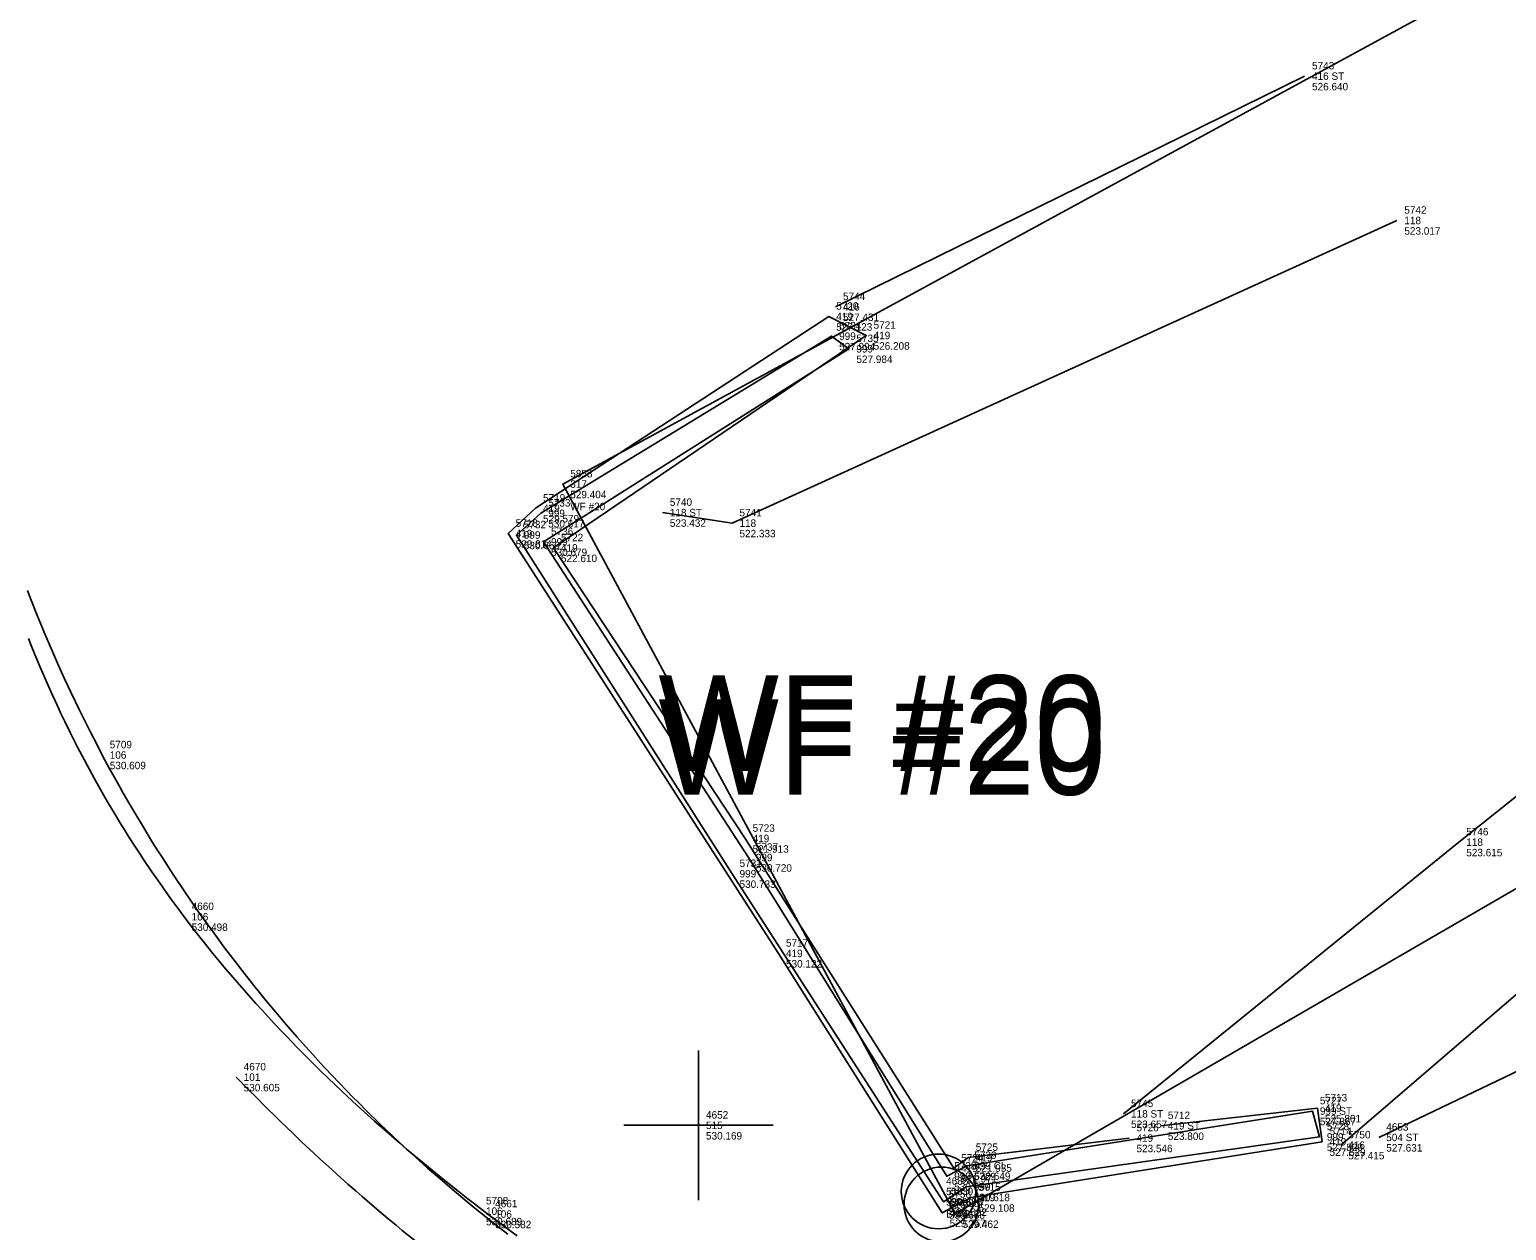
# Model space of a CAD drawing. Extents: x 5447 to 709667, y 4528 to 375505.
# Drawn here: x 705428.87 to 705478.33, y 375271.74 to 375311.93 of the extents above; entities that cross this region are included whole.
import ezdxf

# ---------------------------------------------------------------- set-up
doc = ezdxf.new("R2010")
doc.units = 0
for name, color, linetype in [('SV_BKLN_BKLN', 7, 'Continuous'), ('SV_CTRL_BM', 7, 'Continuous'), ('SV_DRAN_END_WALL', 7, 'Continuous'), ('SV_DRAN_RIPRAP', 7, 'Continuous'), ('SV_GDRL_GR', 7, 'Continuous'), ('SV_NODES_ACTIVE_POINT', 7, 'Continuous'), ('SV_NODES_DESCRIPTION', 7, 'Continuous'), ('SV_NODES_ELEVATION', 7, 'Continuous'), ('SV_NODES_PT_NUMBER', 7, 'Continuous'), ('SV_ROAD_BITRD', 7, 'Continuous'), ('SV_SURF_SPOT', 7, 'Continuous'), ('SV_SURVEY_NOTES', 7, 'Continuous'), ('SV_TREE_TREELN', 7, 'Continuous'), ('SV_WATR_INWETF', 7, 'Continuous'), ('SV_WATR_STREAM', 7, 'Continuous')]:
    doc.layers.add(name, color=color, linetype=linetype)

msp = doc.modelspace()

# ---------------------------------------------------------------- linework, layer by layer
at = {"layer": 'SV_BKLN_BKLN'}
msp.add_lwpolyline([(705471.836, 375275.737), (705472.07, 375274.872), (705460.245, 375273.195), (705459.478, 375272.702), (705452.401, 375283.681), (705445.176, 375295.017), (705445.995, 375295.744), (705455.735, 375301.673), (705456.314, 375301.249), (705446.088, 375294.787), (705452.947, 375284.223), (705459.591, 375273.555), (705460.263, 375273.908), (705471.836, 375275.737)], dxfattribs=at)
at = {"layer": 'SV_CTRL_BM'}
for p, q in [((705459.318, 375273.045), (705459.318, 375273.045)), ((705459.41, 375272.611), (705459.41, 375272.611))]:
    msp.add_line(p, q, dxfattribs=at)
for centre in [(705459.318, 375273.045), (705459.41, 375272.611)]:
    msp.add_circle(centre, 1.25, dxfattribs=at)
at = {"layer": 'SV_DRAN_END_WALL'}
msp.add_lwpolyline([(705466.744, 375275.244), (705472.005, 375275.833), (705472.16, 375274.71), (705460.403, 375272.842), (705459.437, 375272.33), (705453.955, 375281.014), (705444.904, 375295.066), (705445.82, 375295.911), (705455.638, 375302.332), (705456.889, 375301.695), (705446.42, 375294.585), (705452.839, 375284.859), (705459.823, 375273.82), (705460.311, 375274.178), (705465.695, 375274.834)], dxfattribs=at)
at = {"layer": 'SV_DRAN_RIPRAP'}
for points in [[(705471.573, 375310.375), (705455.866, 375302.655)], [(705489.353, 375288.542), (705480.464, 375281.19), (705472.788, 375274.596)]]:
    msp.add_lwpolyline(points, dxfattribs=at)
at = {"layer": 'SV_GDRL_GR'}
for points in [[(705444.893, 375271.617), (705444.498, 375271.922), (705444.302, 375272.076), (705444.041, 375272.283), (705443.911, 375272.388), (705443.531, 375272.697), (705443.028, 375273.117), (705442.779, 375273.329), (705442.532, 375273.543), (705442.203, 375273.83), (705442.04, 375273.975), (705441.555, 375274.414), (705441.235, 375274.71), (705440.812, 375275.11), (705440.602, 375275.311), (705440.134, 375275.77), (705439.929, 375275.975), (705439.656, 375276.251), (705439.52, 375276.39), (705439.217, 375276.705), (705439.017, 375276.916), (705438.752, 375277.199), (705438.62, 375277.341), (705438.358, 375277.628), (705438.012, 375278.013), (705437.841, 375278.207), (705437.459, 375278.647), (705437.175, 375278.98), (705436.802, 375279.427), (705436.618, 375279.653), (705436.343, 375279.993), (705435.982, 375280.451), (705435.803, 375280.681), (705435.406, 375281.204), (705435.21, 375281.467), (705434.952, 375281.82), (705434.823, 375281.998), (705434.569, 375282.354), (705434.236, 375282.833), (705434.071, 375283.075), (705433.705, 375283.621), (705433.525, 375283.896), (705433.287, 375284.264), (705433.17, 375284.449), (705432.995, 375284.728), (705432.765, 375285.101), (705432.651, 375285.289), (705432.397, 375285.713), (705432.231, 375285.997), (705432.012, 375286.378), (705431.903, 375286.569), (705431.663, 375287.001), (705431.544, 375287.217), (705431.387, 375287.508), (705431.31, 375287.653), (705431.133, 375287.989), (705430.901, 375288.439), (705430.787, 375288.665), (705430.534, 375289.175), (705430.41, 375289.431), (705430.247, 375289.774), (705430.167, 375289.946), (705430.047, 375290.205), (705429.89, 375290.551), (705429.812, 375290.724), (705429.64, 375291.116), (705429.527, 375291.377), (705429.379, 375291.727), (705429.306, 375291.902), (705429.145, 375292.298), (705428.909, 375292.894), (705428.807, 375293.16)], [(705428.833, 375291.553), (705428.925, 375291.324), (705429.049, 375291.018), (705429.112, 375290.866), (705429.225, 375290.597), (705429.38, 375290.239), (705429.458, 375290.061), (705429.637, 375289.661), (705429.728, 375289.463), (705429.851, 375289.199), (705429.914, 375289.067), (705430.056, 375288.771), (705430.248, 375288.38), (705430.346, 375288.185), (705430.495, 375287.893), (705430.698, 375287.507), (705430.8, 375287.314), (705431.035, 375286.884), (705431.195, 375286.598), (705431.411, 375286.219), (705431.521, 375286.031), (705431.772, 375285.609), (705431.9, 375285.399), (705432.072, 375285.121), (705432.159, 375284.982), (705432.335, 375284.705), (705432.573, 375284.338), (705432.694, 375284.155), (705432.97, 375283.747), (705433.11, 375283.543), (705433.298, 375283.273), (705433.393, 375283.139), (705433.61, 375282.838), (705433.903, 375282.438), (705434.052, 375282.24), (705434.366, 375281.828), (705434.579, 375281.556), (705434.723, 375281.375), (705435.013, 375281.015), (705435.233, 375280.747), (705435.382, 375280.569), (705435.681, 375280.215), (705435.833, 375280.038), (705436.139, 375279.688), (705436.45, 375279.34), (705436.659, 375279.11), (705437.082, 375278.653), (705437.323, 375278.397), (705437.485, 375278.228), (705437.812, 375277.891), (705437.976, 375277.724), (705438.308, 375277.391), (705438.644, 375277.061), (705438.869, 375276.843), (705439.325, 375276.409), (705439.497, 375276.248), (705439.844, 375275.927), (705440.194, 375275.609), (705440.429, 375275.398), (705440.902, 375274.981), (705441.261, 375274.671), (705441.502, 375274.466), (705441.986, 375274.059), (705442.23, 375273.858), (705442.721, 375273.458), (705443.216, 375273.064), (705443.549, 375272.804), (705443.771, 375272.632), (705444.218, 375272.29), (705444.876, 375271.799), (705445.208, 375271.556)]]:
    msp.add_lwpolyline(points, dxfattribs=at)
at = {"layer": 'SV_NODES_ACTIVE_POINT'}
for p, q in [((705471.573, 375310.375), (705471.573, 375310.375)), ((705474.664, 375305.545), (705474.664, 375305.545)), ((705455.866, 375302.655), (705455.866, 375302.655)), ((705455.638, 375302.332), (705455.638, 375302.332)), ((705455.735, 375301.673), (705455.735, 375301.673)), ((705456.889, 375301.695), (705456.889, 375301.695)), ((705456.314, 375301.249), (705456.314, 375301.249)), ((705446.731, 375296.722), (705446.731, 375296.722)), ((705445.82, 375295.911), (705445.82, 375295.911)), ((705445.995, 375295.744), (705445.995, 375295.744)), ((705450.066, 375295.767), (705450.066, 375295.767)), ((705444.904, 375295.066), (705444.904, 375295.066)), ((705445.176, 375295.017), (705445.176, 375295.017)), ((705452.398, 375295.415), (705452.398, 375295.415)), ((705446.088, 375294.787), (705446.088, 375294.787)), ((705446.42, 375294.585), (705446.42, 375294.585)), ((705431.31, 375287.653), (705431.31, 375287.653)), ((705452.839, 375284.859), (705452.839, 375284.859)), ((705476.737, 375284.738), (705476.737, 375284.738)), ((705452.947, 375284.223), (705452.947, 375284.223)), ((705452.401, 375283.681), (705452.401, 375283.681)), ((705434.052, 375282.24), (705434.052, 375282.24)), ((705453.955, 375281.014), (705453.955, 375281.014)), ((705435.795, 375276.871), (705435.795, 375276.871)), ((705465.513, 375275.644), (705465.513, 375275.644)), ((705471.836, 375275.737), (705471.836, 375275.737)), ((705472.005, 375275.833), (705472.005, 375275.833)), ((705466.744, 375275.244), (705466.744, 375275.244)), ((705465.695, 375274.834), (705465.695, 375274.834)), ((705472.07, 375274.872), (705472.07, 375274.872)), ((705472.16, 375274.71), (705472.16, 375274.71)), ((705474.058, 375274.855), (705474.058, 375274.855)), ((705460.311, 375274.178), (705460.311, 375274.178)), ((705472.788, 375274.596), (705472.788, 375274.596)), ((705459.823, 375273.82), (705459.823, 375273.82)), ((705460.263, 375273.908), (705460.263, 375273.908)), ((705459.591, 375273.555), (705459.591, 375273.555)), ((705460.245, 375273.195), (705460.245, 375273.195)), ((705459.478, 375272.702), (705459.478, 375272.702)), ((705460.403, 375272.842), (705460.403, 375272.842)), ((705443.911, 375272.388), (705443.911, 375272.388)), ((705444.218, 375272.29), (705444.218, 375272.29)), ((705459.437, 375272.33), (705459.437, 375272.33)), ((705459.867, 375272.301), (705459.867, 375272.301))]:
    msp.add_line(p, q, dxfattribs=at)
at = {"layer": 'SV_ROAD_BITRD'}
msp.add_lwpolyline([(705441.774, 375271.401), (705441.356, 375271.742), (705441.147, 375271.914), (705440.87, 375272.144), (705440.732, 375272.26), (705440.423, 375272.522), (705440.012, 375272.875), (705439.808, 375273.053), (705439.536, 375273.292), (705439.176, 375273.613), (705438.996, 375273.775), (705438.594, 375274.141), (705438.394, 375274.326), (705438.128, 375274.574), (705437.995, 375274.699), (705437.698, 375274.981), (705437.303, 375275.361), (705437.107, 375275.552), (705436.813, 375275.841), (705436.424, 375276.23), (705436.23, 375276.426), (705435.795, 375276.871)], dxfattribs=at)
at = {"layer": 'SV_SURF_SPOT'}
for p, q in [((705451.277, 375272.758), (705451.277, 375277.76)), ((705448.776, 375275.259), (705453.778, 375275.259)), ((705451.277, 375275.259), (705451.277, 375275.259))]:
    msp.add_line(p, q, dxfattribs=at)
at = {"layer": 'SV_TREE_TREELN'}
msp.add_lwpolyline([(705474.058, 375274.855), (705495.162, 375284.95), (705524.723, 375284.239), (705558.01, 375282.679), (705583.345, 375279.879), (705602.913, 375276.221)], dxfattribs=at)
at = {"layer": 'SV_WATR_INWETF'}
msp.add_lwpolyline([(705578.39, 375331.311), (705524.349, 375309.659), (705459.867, 375272.301), (705446.731, 375296.722), (705543.238, 375349.235), (705597.77, 375381.862)], dxfattribs=at)
at = {"layer": 'SV_WATR_STREAM'}
for points in [[(705450.066, 375295.767), (705452.398, 375295.415), (705474.664, 375305.545)], [(705465.513, 375275.644), (705476.737, 375284.738), (705486.336, 375292.375)]]:
    msp.add_lwpolyline(points, dxfattribs=at)

# ---------------------------------------------------------------- texts
at = {"layer": 'SV_NODES_DESCRIPTION'}
for s, p in [('416 ST', (705471.823, 375310.25)), ('118', (705474.914, 375305.42)), ('419', (705455.888, 375302.207)), ('416', (705456.115, 375302.529)), ('999', (705455.985, 375301.548)), ('999', (705456.564, 375301.124)), ('419', (705457.139, 375301.57)), ('317', (705446.981, 375296.597)), ('419', (705446.07, 375295.786)), ('999', (705446.244, 375295.619)), ('118 ST', (705450.316, 375295.642)), ('118', (705452.648, 375295.29)), ('419', (705445.153, 375294.941)), ('999', (705445.425, 375294.892)), ('999', (705446.338, 375294.662)), ('419', (705446.67, 375294.46)), ('106', (705431.559, 375287.528)), ('419', (705453.088, 375284.734)), ('118', (705476.987, 375284.613)), ('999', (705453.196, 375284.098)), ('999', (705452.651, 375283.556)), ('106', (705434.302, 375282.115)), ('419', (705454.205, 375280.889)), ('101', (705436.045, 375276.746)), ('118 ST', (705465.762, 375275.519)), ('999 ST', (705472.085, 375275.612)), ('419', (705472.254, 375275.708)), ('515', (705451.527, 375275.134)), ('419 ST', (705466.994, 375275.119)), ('419', (705465.944, 375274.709)), ('999', (705472.319, 375274.747)), ('419', (705472.41, 375274.585)), ('416', (705473.037, 375274.471)), ('504 ST', (705474.308, 375274.73)), ('419', (705460.561, 375274.053)), ('999', (705459.84, 375273.43)), ('419', (705460.073, 375273.695)), ('999 CL', (705460.512, 375273.783)), ('516', (705459.568, 375272.92)), ('999', (705460.495, 375273.07)), ('516', (705459.66, 375272.486)), ('999', (705459.728, 375272.577)), ('419', (705460.652, 375272.717)), ('106', (705444.161, 375272.262)), ('106', (705444.468, 375272.165)), ('419', (705459.686, 375272.205)), ('317', (705460.116, 375272.176))]:
    msp.add_text(s, height=0.25, dxfattribs=at).set_placement(p)
at = {"layer": 'SV_NODES_ELEVATION'}
for s, p in [('526.640', (705471.823, 375309.9)), ('523.017', (705474.914, 375305.07)), ('527.431', (705456.115, 375302.179)), ('527.123', (705455.888, 375301.857)), ('527.994', (705455.985, 375301.198)), ('526.208', (705457.139, 375301.22)), ('527.984', (705456.564, 375300.774)), ('529.404', (705446.981, 375296.247)), ('529.579', (705446.07, 375295.436)), ('530.617', (705446.244, 375295.269)), ('523.432', (705450.316, 375295.292)), ('522.333', (705452.648, 375294.94)), ('529.814', (705445.153, 375294.591)), ('530.669', (705445.425, 375294.542)), ('530.679', (705446.338, 375294.312)), ('522.610', (705446.67, 375294.11)), ('530.609', (705431.559, 375287.178)), ('521.913', (705453.088, 375284.384)), ('523.615', (705476.987, 375284.263)), ('530.720', (705453.196, 375283.748)), ('530.733', (705452.651, 375283.206)), ('530.498', (705434.302, 375281.765)), ('530.122', (705454.205, 375280.539)), ('530.605', (705436.045, 375276.396)), ('523.657', (705465.762, 375275.169)), ('527.867', (705472.085, 375275.262)), ('525.801', (705472.254, 375275.358)), ('530.169', (705451.527, 375274.784)), ('523.800', (705466.994, 375274.769)), ('523.546', (705465.944, 375274.359)), ('527.829', (705472.319, 375274.397)), ('527.529', (705472.41, 375274.235)), ('527.415', (705473.037, 375274.121)), ('527.631', (705474.308, 375274.38)), ('530.649', (705460.512, 375273.433)), ('521.935', (705460.561, 375273.703)), ('530.650', (705459.84, 375273.08)), ('521.971', (705460.073, 375273.345)), ('530.636', (705459.568, 375272.57)), ('530.618', (705460.495, 375272.72)), ('530.688', (705459.66, 375272.136)), ('530.682', (705459.728, 375272.227)), ('529.108', (705460.652, 375272.367)), ('530.689', (705444.161, 375271.912)), ('530.582', (705444.468, 375271.815)), ('529.757', (705459.686, 375271.855)), ('529.462', (705460.116, 375271.826))]:
    msp.add_text(s, height=0.25, dxfattribs=at).set_placement(p)
at = {"layer": 'SV_NODES_PT_NUMBER'}
for s, p in [('5743', (705471.823, 375310.6)), ('5742', (705474.914, 375305.77)), ('5744', (705456.115, 375302.879)), ('5720', (705455.888, 375302.557)), ('5734', (705455.985, 375301.898)), ('5721', (705457.139, 375301.92)), ('5735', (705456.564, 375301.474)), ('5858', (705446.981, 375296.947)), ('5719', (705446.07, 375296.136)), ('5733', (705446.244, 375295.969)), ('5740', (705450.316, 375295.992)), ('5718', (705445.153, 375295.291)), ('5732', (705445.425, 375295.242)), ('5741', (705452.648, 375295.64)), ('5736', (705446.338, 375295.012)), ('5722', (705446.67, 375294.81)), ('5709', (705431.559, 375287.878)), ('5723', (705453.088, 375285.084)), ('5746', (705476.987, 375284.963)), ('5737', (705453.196, 375284.448)), ('5731', (705452.651, 375283.906)), ('4660', (705434.302, 375282.465)), ('5717', (705454.205, 375281.239)), ('4670', (705436.045, 375277.096)), ('5727', (705472.085, 375275.962)), ('5713', (705472.254, 375276.058)), ('4652', (705451.527, 375275.484)), ('5745', (705465.762, 375275.869)), ('5712', (705466.994, 375275.469)), ('5726', (705465.944, 375275.059)), ('5728', (705472.319, 375275.097)), ('5714', (705472.41, 375274.935)), ('4653', (705474.308, 375275.08)), ('5725', (705460.561, 375274.403)), ('5750', (705473.037, 375274.821)), ('5724', (705460.073, 375274.045)), ('5739', (705460.512, 375274.133)), ('5738', (705459.84, 375273.78)), ('5729', (705460.495, 375273.42)), ('4685', (705459.568, 375273.27)), ('5730', (705459.728, 375272.927)), ('5715', (705460.652, 375273.067)), ('5708', (705444.161, 375272.612)), ('4661', (705444.468, 375272.515)), ('5758', (705459.66, 375272.836)), ('5716', (705459.686, 375272.555)), ('5857', (705460.116, 375272.526))]:
    msp.add_text(s, height=0.25, dxfattribs=at).set_placement(p)
at = {"layer": 'SV_SURVEY_NOTES'}
for s, height, p in [('WF #20', 0.25, (705446.981, 375295.847)), ('WF #20', 3.2, (705449.931, 375287.122)), ('WF #20', 3.2, (705449.931, 375287.122)), ('WF #20', 3.2, (705449.931, 375287.122)), ('WF #20', 3.2, (705449.931, 375287.122)), ('WF #20', 3.2, (705449.931, 375287.122)), ('WF #20', 3.2, (705449.931, 375287.122)), ('WF #20', 3.2, (705449.931, 375287.122)), ('WF #20', 3.2, (705449.931, 375287.122)), ('WF #20', 3.2, (705449.931, 375286.322)), ('WF #20', 3.2, (705449.931, 375286.322)), ('WF #20', 3.2, (705449.931, 375286.322)), ('BM-2', 0.25, (705459.568, 375272.17))]:
    msp.add_text(s, height=height, dxfattribs=at).set_placement(p)

doc.saveas('drawing.dxf')
